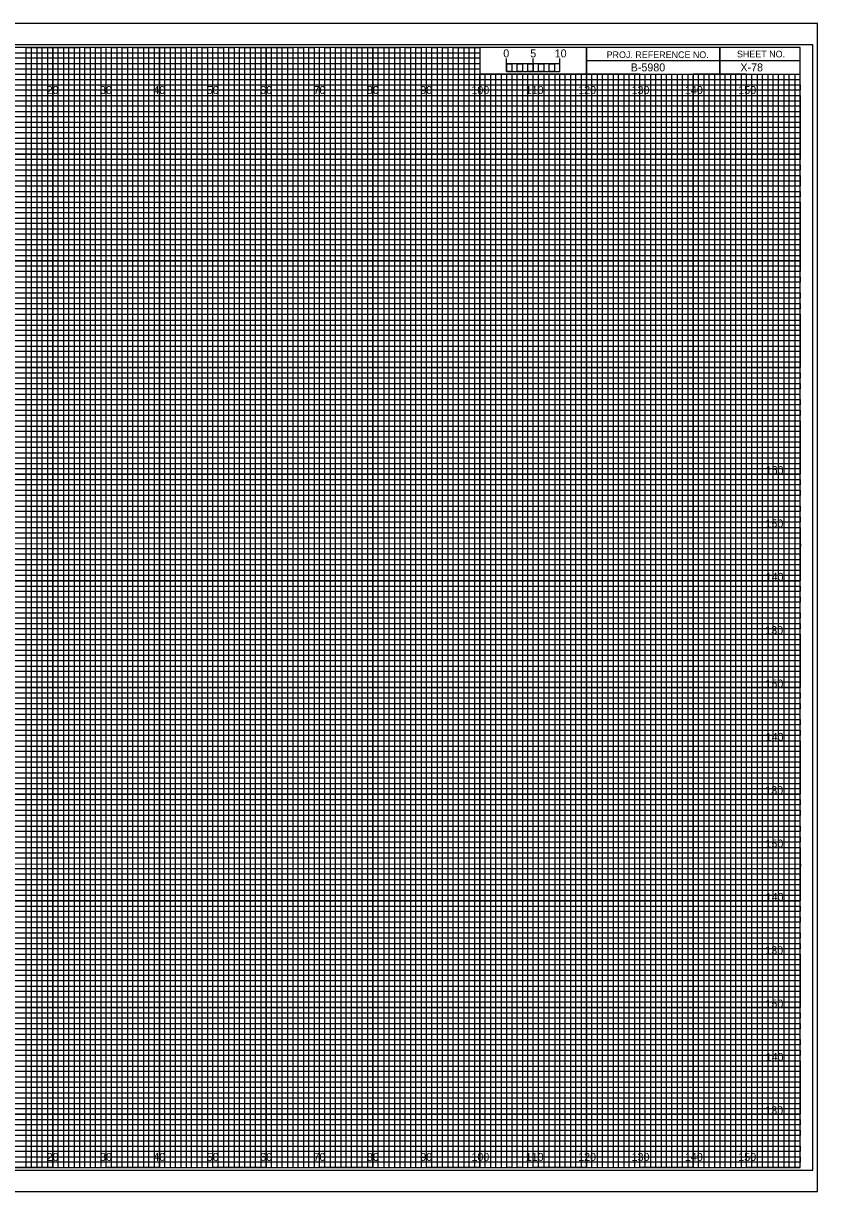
# Model space of a CAD drawing. Extents: x -13 to 323, y -5 to 434.
# Drawn here: x 174.5 to 323.3, y 215.5 to 434.5 of the extents above; entities that cross this region are included whole.
import ezdxf

# ---------------------------------------------------------------- set-up
doc = ezdxf.new("R2010")
doc.units = 0
for name, color, linetype in [('Exist Cross Section Cell', 7, 'Continuous'), ('Exist XS Center Line Elevation Label', 7, 'Continuous'), ('Exist XS Ground Line', 7, 'Continuous'), ('Prop CMT Guardrail Widen Shoulder', 7, 'Continuous'), ('Prop CMT Pvmt Course 1', 7, 'Continuous'), ('Prop CMT Pvmt Course 2', 7, 'Continuous'), ('Prop CMT Pvmt Course 3', 7, 'Continuous'), ('Prop CMT Pvmt Surface', 7, 'Continuous'), ('Prop CMT Pvmt Surface Shoulder', 7, 'Continuous'), ('Prop CMT Shld Paved Course 1', 7, 'Continuous'), ('Prop CMT Shld Paved Course 2', 7, 'Continuous'), ('Prop CMT Shld Paved Course 3', 7, 'Continuous'), ('Prop CMT Subgrade Earthwork', 7, 'Continuous'), ('Prop XS SE Text', 7, 'Continuous'), ('Scratch_Level_0', 7, 'Continuous')]:
    doc.layers.add(name, color=color, linetype=linetype)

msp = doc.modelspace()

# ---------------------------------------------------------------- linework, layer by layer
at = {"layer": 'Exist XS Center Line Elevation Label'}
for points in [[(165, 220), (175, 220), (175, 430), (185, 430), (185, 220), (195, 220), (195, 430), (205, 430), (205, 220), (215, 220), (215, 430), (225, 430), (225, 220), (235, 220), (235, 430), (245, 430), (245, 220), (255, 220), (255, 430), (259.93, 430), (260, 430), (260, 425), (264.99, 425), (264.99, 220), (275, 220), (275, 425), (285, 425), (285, 220), (295, 220), (295, 425), (305, 425), (305, 220), (315, 220), (315, 425)], [(0, 425), (275, 425)], [(0, 405), (320, 405), (320, 415), (0, 415)], [(0, 385), (320, 385), (320, 395), (0, 395)], [(0, 365), (320, 365), (320, 375), (0, 375)], [(0, 345), (320, 345), (320, 355), (0, 355)], [(0, 325), (320, 325), (320, 335), (0, 335)], [(0, 305), (320, 305), (320, 315), (0, 315)], [(0, 285), (320, 285), (320, 295), (0, 295)], [(0, 265), (320, 265), (320, 275), (0, 275)], [(0, 245), (320, 245), (320, 255), (0, 255)], [(0, 225), (320, 225), (320, 235), (0, 235)]]:
    msp.add_lwpolyline(points, dxfattribs=at)
at = {"layer": 'Exist XS Ground Line'}
for p, q in [((190, 430), (180, 430)), ((180, 430), (180, 220)), ((190, 220), (190, 430)), ((210, 430), (200, 430)), ((200, 430), (200, 220)), ((210, 220), (210, 430)), ((230, 430), (220, 430)), ((220, 430), (220, 220)), ((230, 220), (230, 430)), ((250, 430), (240, 430)), ((240, 430), (240, 220)), ((250, 220), (250, 430)), ((260, 430), (260, 220)), ((270, 220), (270, 425)), ((290, 425), (280, 425)), ((280, 425), (280, 220)), ((290, 220), (290, 425)), ((310, 425), (300, 425)), ((300, 425), (300, 220)), ((310, 220), (310, 425)), ((180, 220), (170, 220)), ((200, 220), (190, 220)), ((220, 220), (210, 220)), ((240, 220), (230, 220)), ((260, 220), (250, 220)), ((280, 220), (270, 220)), ((300, 220), (290, 220)), ((320, 220), (310, 220)), ((320, 220), (320, 220))]:
    msp.add_line(p, q, dxfattribs=at)
for points in [[(0, 420), (320, 420), (320, 410), (0, 410)], [(0, 400), (320, 400), (320, 390), (0, 390)], [(0, 380), (320, 380), (320, 370), (0, 370)], [(0, 360), (320, 360), (320, 350), (0, 350)], [(0, 340), (320, 340), (320, 330), (0, 330)], [(0, 320), (320, 320), (320, 310), (0, 310)], [(0, 300), (320, 300), (320, 290), (0, 290)], [(0, 280), (320, 280), (320, 270), (0, 270)], [(0, 260), (320, 260), (320, 250), (0, 250)], [(0, 240), (320, 240), (320, 230), (0, 230)]]:
    msp.add_lwpolyline(points, dxfattribs=at)
at = {"layer": 'Prop CMT Pvmt Course 2'}
for p, q in [((265, 425.49), (265, 427.9)), ((265, 426.9), (265, 427.9)), ((270, 425.49), (270, 427.9)), ((275, 425.49), (275, 427.9)), ((275, 426.9), (275, 427.9))]:
    msp.add_line(p, q, dxfattribs=at)
for points in [[(275, 426.9), (265, 426.9), (265, 425.49), (275, 425.49)], [(265, 426.9), (266, 426.9), (266, 425.49), (265, 425.49)], [(267, 426.9), (268, 426.9), (268, 425.49), (267, 425.49)], [(269, 426.9), (270, 426.9), (270, 425.49), (269, 425.49)], [(271, 426.9), (272, 426.9), (272, 425.49), (271, 425.49)], [(273, 426.9), (274, 426.9), (274, 425.49), (273, 425.49)]]:
    msp.add_lwpolyline(points, close=True, dxfattribs=at)
at = {"layer": 'Prop CMT Pvmt Course 3'}
msp.add_lwpolyline([(-13.4, 215.5), (323.3, 215.5), (323.3, 434.5), (-13.4, 434.5)], close=True, dxfattribs=at)
at = {"layer": 'Prop CMT Pvmt Surface'}
for p, q in [((180, 220), (180, 430)), ((190, 220), (190, 430)), ((200, 220), (200, 430)), ((210, 220), (210, 430)), ((220, 220), (220, 430)), ((230, 220), (230, 430)), ((240, 220), (240, 430)), ((250, 220), (250, 430)), ((260, 220), (260, 424.69)), ((270, 220), (270, 424.69)), ((280, 220), (280, 424.69)), ((290, 220), (290, 424.69)), ((300, 220), (300, 424.69)), ((310, 220), (310, 424.69)), ((0, 420), (320, 420)), ((0, 410), (320, 410)), ((0, 400), (320, 400)), ((0, 390), (320, 390)), ((0, 380), (320, 380)), ((0, 370), (320, 370)), ((0, 360), (320, 360)), ((0, 350), (320, 350)), ((0, 340), (320, 340)), ((0, 330), (320, 330)), ((0, 320), (320, 320)), ((0, 310), (320, 310)), ((0, 300), (320, 300)), ((0, 290), (320, 290)), ((0, 280), (320, 280)), ((0, 270), (320, 270)), ((0, 260), (320, 260)), ((0, 250), (320, 250)), ((0, 240), (320, 240)), ((0, 230), (320, 230))]:
    msp.add_line(p, q, dxfattribs=at)
at = {"layer": 'Prop CMT Pvmt Surface Shoulder'}
for p, q in [((323.3, 434.5), (-13.4, 434.5)), ((-13.4, 215.5), (323.3, 215.5))]:
    msp.add_line(p, q, dxfattribs=at)
at = {"layer": 'Prop CMT Shld Paved Course 1'}
for p, q in [((0, 429), (260, 429)), ((260, 427.98), (0, 427.98)), ((260, 429), (260, 427.98)), ((0, 427), (260, 427)), ((260, 425.89), (0, 425.89)), ((260, 427), (260, 425.89)), ((0, 424), (320, 424))]:
    msp.add_line(p, q, dxfattribs=at)
for points in [[(0, 423), (270, 423), (320, 423), (320, 422), (0, 422)], [(0, 421), (320, 421), (320, 419), (0, 419)], [(0, 418), (320, 418), (320, 417), (0, 416.98)], [(0, 416), (320, 416), (320, 414), (0, 414)], [(0, 413), (320, 413), (320, 412), (0, 412)], [(0, 411), (320, 411), (320, 409), (0, 409)], [(0, 408), (320, 408), (320, 407), (0, 407)], [(0, 406), (320, 406), (320, 404), (0, 404)], [(0, 403), (320, 403), (320, 402), (0, 402)], [(0, 401), (320, 401), (320, 399), (0, 399)], [(0, 398), (320, 398), (320, 397), (0, 397)], [(0, 396), (320, 396), (320, 393.95), (320, 393), (320, 392), (0, 392)], [(0, 394), (320, 394), (320, 393), (0, 393)], [(0, 391), (320, 391), (320, 389), (0, 389.03)], [(0, 389.03), (320, 389), (320, 388), (0, 388)], [(0, 387), (320, 387), (320, 386), (0, 386)], [(0, 384), (320, 384), (320, 383), (0, 383)], [(0, 382), (320, 382), (320, 381), (0, 381)], [(-0.07, 378.89), (320, 378.89), (320, 377.88), (-0.07, 377.88)], [(0, 377), (320, 377), (320, 376), (0, 376)], [(0, 374), (320, 374), (320, 373), (0, 373)], [(0, 372), (320, 372), (320, 371), (0, 371)], [(0, 369), (320, 369), (320, 368), (0, 368)], [(0, 367), (320, 367), (320, 366), (0, 366)], [(0, 364), (320, 364), (320, 363), (0, 363)], [(0, 362), (320, 362), (320, 361), (0, 361)], [(0, 359), (320, 359), (319.99, 357.98), (0, 358)], [(0, 357), (320, 357), (320, 356), (0, 356)], [(0, 354), (320, 354), (320, 353), (0, 353)], [(0, 352), (320, 352), (320, 351), (0, 351)], [(0, 349), (320, 349), (320, 348), (0, 348)], [(0, 347), (320, 347), (320, 346), (0, 346)], [(0, 344), (320, 344), (320, 343), (0, 343)], [(0, 342), (320, 342), (320, 341), (0, 341)], [(0, 339), (320, 339), (320, 338), (0, 338)], [(0, 336.99), (320.07, 336.91), (320, 336), (0, 336)], [(0, 334), (320, 334), (320, 333), (0, 333)], [(0, 332), (320, 332), (320, 331), (0, 331)], [(0, 329), (320, 329), (320, 328), (0, 328)], [(0, 327), (320, 327), (320, 326), (0, 326)], [(0, 324), (320, 324), (320, 323), (0, 323)], [(0, 322), (320, 322), (320, 321), (0, 321)], [(0, 319), (320, 319), (320, 318), (0, 318)], [(0, 317), (320, 317), (320, 316), (0, 316)], [(0, 314), (320, 314), (320, 313), (0, 313)], [(0, 312), (320, 312), (320, 311), (0, 311)], [(0, 309), (320, 309), (320, 308), (0, 308)], [(0, 307), (320, 307), (320, 306), (0, 306)], [(0, 304), (320, 304), (320, 303), (0, 303)], [(0, 302), (320, 302), (320, 301), (0, 301)], [(0, 299), (320, 299), (319.99, 297.98), (0, 298)], [(0, 297), (320, 297), (320, 296), (0, 296)], [(0, 294), (320, 294), (320, 293), (0, 293)], [(0, 292), (320, 292), (320, 291), (0, 291)], [(0, 289), (320, 289), (320, 288), (0, 288)], [(0, 287), (320, 287), (320, 286), (0, 286)], [(0, 284), (320, 284), (320, 283), (0, 283)], [(0, 282), (320, 282), (320, 281), (0, 281)], [(0, 279), (320, 279), (320, 278), (0, 278)], [(0, 276.99), (320.07, 276.91), (320, 276), (0, 276)], [(0, 274), (320, 274), (320, 273), (0, 273)], [(0, 272), (320, 272), (320, 271), (0, 271)], [(0, 269), (320, 269), (320, 268), (0, 268)], [(0, 267), (320, 267), (320, 266), (0, 266)], [(0, 264), (320, 264), (320, 263), (0, 263)], [(0, 262), (320, 262), (320, 261), (0, 261)], [(0, 259), (320, 259), (320, 258), (0, 258)], [(0, 257), (320, 257), (320, 256), (0, 256)], [(0, 254), (320, 254), (320, 253), (0, 253)], [(0, 252), (320, 252), (320, 251), (0, 251)], [(0, 249), (320, 249), (320, 248), (0, 248)], [(0, 247), (320, 247), (320, 246), (0, 246)], [(0, 244), (320, 244), (320, 243), (0, 243)], [(0, 242), (320, 242), (320, 241), (0, 241)], [(0, 239), (320, 239), (320, 238), (0, 238)], [(0, 237), (320, 237), (320, 236), (0, 236)], [(0, 234), (320, 234), (320, 233), (0, 233)], [(0, 232), (320, 232), (320, 231), (0, 231)], [(0, 229), (320, 229), (320, 228), (0, 228)], [(0, 227), (320, 227), (320, 226), (0, 226)], [(0, 224), (320, 224), (320, 223), (0, 223)], [(0, 222), (320, 222), (320, 221), (0, 221)]]:
    msp.add_lwpolyline(points, dxfattribs=at)
at = {"layer": 'Prop CMT Shld Paved Course 2'}
for p, q in [((305, 430), (305, 425)), ((305, 425), (305, 430)), ((280, 427.5), (280, 425)), ((320, 427.49), (280, 427.49)), ((280, 425), (320, 425))]:
    msp.add_line(p, q, dxfattribs=at)
for points in [[(320, 430), (0, 430), (0, 220), (320, 220)], [(280, 430), (260, 430), (260, 425.03), (280, 425.03)], [(320, 430), (280, 430), (280, 425), (320, 425)]]:
    msp.add_lwpolyline(points, close=True, dxfattribs=at)
at = {"layer": 'Prop CMT Shld Paved Course 3'}
for p, q in [((267, 425), (266.01, 425)), ((266.01, 425), (266.01, 220)), ((267, 220), (267, 425)), ((269, 425), (268, 425)), ((268, 425), (268, 220)), ((269, 220), (269, 425)), ((266.01, 220), (265, 220)), ((268, 220), (267, 220))]:
    msp.add_line(p, q, dxfattribs=at)
for points in [[(175, 220), (176, 220), (176, 430), (177, 430), (177, 220)], [(177, 220), (178, 220), (178, 430), (179, 430), (179, 220)], [(180, 220), (181, 220), (181, 430), (182, 430), (182, 220)], [(182, 220), (183, 220), (183, 430), (184, 430), (184, 220)], [(185, 220), (186, 220), (186, 430), (187, 430), (187, 220)], [(187, 220), (188, 220), (188, 430), (189, 430), (189, 220)], [(190, 220), (191, 220), (191, 430), (192, 430), (192, 220)], [(192, 220), (193, 220), (193, 430), (194, 430), (194, 220)], [(195, 220), (196, 220), (196, 430), (197, 430), (197, 220)], [(197, 220), (198, 220), (198, 430), (199, 430), (199, 220)], [(200, 220), (201, 220), (201, 430), (202, 430), (202, 220)], [(202, 220), (203, 220), (203, 430), (204, 430), (204, 220)], [(205, 220), (206, 220), (206, 430), (207, 430), (207, 220)], [(207, 220), (208, 220), (208, 430), (209, 430), (209, 220)], [(210, 220), (211, 220), (211, 430), (212, 430), (212, 220)], [(212, 220), (213, 220), (213, 430), (214, 430), (214, 220)], [(215, 220), (216, 220), (216, 430), (217, 430), (217, 220)], [(217, 220), (218, 220), (218, 430), (219, 430), (219, 220)], [(220, 220), (221, 220), (221, 430), (222, 430), (222, 220)], [(222, 220), (223, 220), (223, 430), (224, 430), (224, 220)], [(225, 220), (226, 220), (226, 430), (227, 430), (227, 220)], [(227, 220), (228, 220), (228, 430), (229, 430), (229, 220)], [(230, 220), (231, 220), (231, 430), (232, 430), (232, 220)], [(232, 220), (233, 220), (233, 430), (234, 430), (234, 220)], [(235, 220), (236, 220), (236, 430), (237, 430), (237, 220)], [(237, 220), (238, 220), (238, 430), (239, 430), (239, 220)], [(240, 220), (241, 220), (241, 430), (242, 430), (242, 220)], [(242, 220), (243, 220), (243, 430), (244, 430), (244, 220)], [(245, 220), (246, 220), (246, 430), (247, 430), (247, 220)], [(247, 220), (248, 220), (248, 430), (249, 430), (249, 220)], [(250, 220), (251, 220), (251, 430), (252, 430), (252, 220)], [(252, 220), (253, 220), (253, 430), (254, 430), (254, 220)], [(255, 220), (256, 220), (256, 430), (257, 430), (257, 220)], [(257, 220), (258, 220), (258, 430), (259, 430), (259, 220)], [(260, 220), (261, 220), (261, 425), (262.02, 425), (262.02, 220)], [(262, 220), (263, 220), (263, 425), (263.99, 425), (263.99, 220)], [(270, 220), (270.98, 220), (270.98, 425), (272, 425), (272, 220)], [(272, 220), (273, 220), (273, 425), (274.05, 425), (274.05, 220)], [(275, 220), (276, 220), (276, 425), (277, 425), (277, 220)], [(277, 220), (278, 220), (278, 425), (279, 425), (279, 220)], [(280, 220), (281, 220), (281, 425), (282, 425), (282, 220)], [(282, 220), (283, 220), (283, 425), (284, 425), (284, 220)], [(285, 220), (286, 220), (286, 425), (287, 425), (287, 220)], [(287, 220), (288, 220), (288, 425), (289, 425), (289, 220)], [(290, 220), (291, 220), (291, 425), (292, 425), (292, 220)], [(292, 220), (293, 220), (293, 425), (294, 425), (294, 220)], [(295, 220), (296, 220), (296, 425), (297, 425), (297, 220)], [(297, 220), (298, 220), (298, 425), (299, 425), (299, 220)], [(300, 220), (301, 220), (301, 425), (302, 425), (302, 220)], [(302, 220), (303, 220), (303, 425), (304, 425), (304, 220)], [(305, 220), (306, 220), (306, 425), (307, 425), (307, 220)], [(307, 220), (308, 220), (308, 425), (309, 425), (309, 220)], [(310, 220), (311, 220), (311, 425), (312, 425), (312, 220)], [(312, 220), (313, 220), (313, 425), (314, 425), (314, 220)], [(315, 220), (316, 220), (316, 425), (317, 425), (317, 220)], [(317, 220), (318, 220), (318, 425), (319, 425), (319, 220)]]:
    msp.add_lwpolyline(points, dxfattribs=at)
at = {"layer": 'Prop CMT Subgrade Earthwork'}
msp.add_lwpolyline([(-10.8, 219.5), (322.4, 219.5), (322.4, 430.5), (-10.8, 430.5)], close=True, dxfattribs=at)

# ---------------------------------------------------------------- texts
at = {"layer": 'Exist Cross Section Cell'}
for s, p in [('20', (178.86, 421.25)), ('30', (188.86, 421.25)), ('40', (198.86, 421.25)), ('50', (208.86, 421.25)), ('60', (218.86, 421.25)), ('70', (228.86, 421.25)), ('80', (238.86, 421.25)), ('90', (248.86, 421.25)), ('100', (258.44, 421.25)), ('110', (268.62, 421.25)), ('120', (278.44, 421.25)), ('130', (288.44, 421.25)), ('140', (298.44, 421.25)), ('150', (308.44, 421.25)), ('20', (178.86, 221.25)), ('30', (188.86, 221.25)), ('40', (198.86, 221.25)), ('50', (208.86, 221.25)), ('60', (218.86, 221.25)), ('70', (228.86, 221.25)), ('80', (238.86, 221.25)), ('90', (248.86, 221.25)), ('100', (258.44, 221.25)), ('110', (268.62, 221.25)), ('120', (278.44, 221.25)), ('130', (288.44, 221.25)), ('140', (298.44, 221.25)), ('150', (308.44, 221.25))]:
    msp.add_text(s, height=1.5, dxfattribs=at).set_placement(p)
at = {"layer": 'Prop CMT Guardrail Widen Shoulder'}
msp.add_text('X-78', height=1.5, dxfattribs=at).set_placement((308.83, 425.5))
at = {"layer": 'Prop CMT Pvmt Course 1'}
for s, p in [('160', (313.57, 350)), ('150', (313.52, 340)), ('140', (313.57, 330)), ('130', (313.49, 320)), ('150', (313.52, 310)), ('140', (313.57, 300)), ('130', (313.49, 290)), ('150', (313.52, 280)), ('140', (313.57, 270)), ('130', (313.49, 260)), ('150', (313.52, 250)), ('140', (313.57, 240)), ('130', (313.49, 230))]:
    msp.add_text(s, height=1.5, dxfattribs=at).set_placement(p)
at = {"layer": 'Prop CMT Pvmt Course 2'}
msp.add_text('0', height=1.5, dxfattribs=at).set_placement((264.41, 428.12))
at = {"layer": 'Prop CMT Shld Paved Course 2'}
for s, p in [('PROJ. REFERENCE NO.', (283.77, 427.99)), ('SHEET NO.', (308.19, 428.12))]:
    msp.add_text(s, height=1.25, dxfattribs=at).set_placement(p)
at = {"layer": 'Prop XS SE Text'}
for s, p in [('5', (269.47, 428.12)), ('10', (274.04, 428.12))]:
    msp.add_text(s, height=1.5, dxfattribs=at).set_placement(p)
at = {"layer": 'Scratch_Level_0'}
msp.add_text('B-5980', height=1.5, dxfattribs=at).set_placement((288.28, 425.5))

doc.saveas('drawing.dxf')
